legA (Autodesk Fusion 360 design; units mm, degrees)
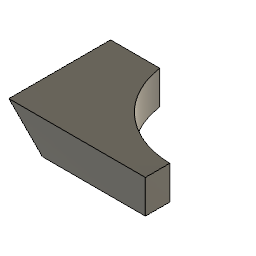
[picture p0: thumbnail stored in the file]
sketch "Sketch2" plane through (0, 0, 0) normal (0, 0, 1) x axis (1, 0, 0)
  line L1 (34.0614, 1.7525) -> (0, 1.7525)
  line L2 (34.0614, 7.8862) -> (34.0614, 1.7525)
  line L3 (0, 27.1525) -> (12.2674, 27.1525)
  line L4 (0, 1.7525) -> (0, 27.1525)
  arc A1 centre (34.4882, 30.3289) radius 22.4467 clockwise from (34.0614, 7.8862) to (12.2674, 27.1525)
  point P2 (0, 1.7525)
  point P3 (34.0614, 1.7525)
  point P4 (0, 27.1525)
  horizontal L1
  vertical L2
  horizontal L3
  vertical L4
  dimension "d1" distance P2 P3 = 34.0614
  dimension "d2" distance P2 P4 = 25.4
extrude "Extrude1" new body sketch "Sketch2" along normal blind 8.382
sketch "Sketch3" plane through (0, 27.1525, 0) normal (0, 1, 0) x axis (-1, 0, 0)
  line L1 (0, 0) -> (-12.2674, 0)
  line L2 (0, 8.382) -> (0, 0)
  line L3 (-12.2674, 8.382) -> (0, 8.382)
  line L4 (-12.2674, 0) -> (-12.2674, 8.382)
  line L5 (-8.382, 0) -> (0, 0)
  line L6 (0, 0) -> (0, 8.382)
  line L7 (-8.382, 0) -> (0, 8.382)
  point P3 (0, 0)
  point P6 (0, 0)
  point P4 (0, 8.382)
  point P9 (0, 8.382)
  point P7 (-8.382, 0)
  point P8 (0, 8.382)
  horizontal L5
  vertical L6
  coincident P3 P6
  coincident P4 P9
  dimension "d5" distance P6 P7 = 8.382
  dimension "d6" distance P6 P8 = 8.382
split "Split1"
remove_body "RemoveBody1"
